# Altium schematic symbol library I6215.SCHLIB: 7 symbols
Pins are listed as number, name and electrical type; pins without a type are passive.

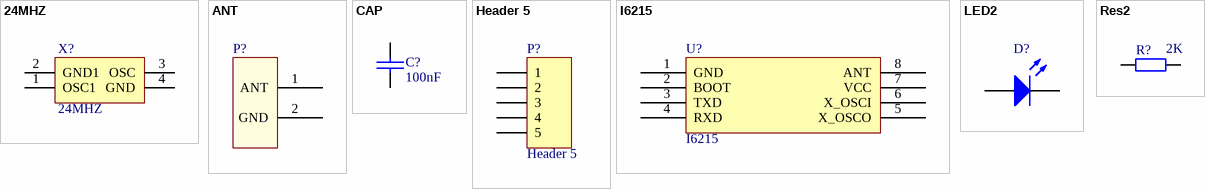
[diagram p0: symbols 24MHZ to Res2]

## 24MHZ
designator X?
value: 12MHZ
footprint crystal oscillator 24MHZ
pins: 1 OSC1, 2 GND1, 3 OSC, 4 GND

## ANT
designator P?  (value not drawn)
footprint ANT-F-1-2.4G-1.0mmFR4-WCH-KC
pins: 1 ANT, 2 GND

## CAP
designator C?, comment 100nF
Capacitor; Value: 1.2pF
footprint 0402_C
pins: 1, 2

## Header 5
designator P?
Header, 5-Pin
footprint HDR1X5 (Connector; Header; 5 Position)
signal-integrity model Connector
pins: 1, 2, 3, 4, 5

## I6215
designator U?
footprint SOP8
pins: 1 GND, 2 BOOT, 3 TXD, 4 RXD, 5 X_OSCO, 6 X_OSCI, 7 VCC, 8 ANT

## LED2
designator D?, comment LED  (value not drawn)
Typical RED, GREEN, YELLOW, AMBER GaAs LED
footprint LED0402-RD_RED
simulation model LED2 (Diode)
pins: 1 A, 2 K

## Res2
designator R?, comment 2K
Resistor
footprint 0805
simulation model RESISTOR (Resistor)
signal-integrity model Res
footprint 0805
footprint 0603
footprint 0402_R
pins: 1, 2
